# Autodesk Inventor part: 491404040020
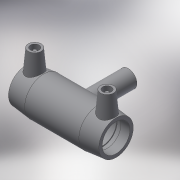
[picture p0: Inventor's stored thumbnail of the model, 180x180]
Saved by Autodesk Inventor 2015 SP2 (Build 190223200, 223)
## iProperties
Created: 2017-06
Part Number: 491404040020
Material: Generic
Description: PLASSON REDUCING TEE 40x20x40
Document SubType Name: Modeling
Designer: KIM
Mass: 57.3761 g
Surface Area: 241.06 cm^2
Volume: 57.3761 cm^3
Density: 1 g/cm^3
Appearance: Default
Author: KIM
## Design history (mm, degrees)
derived "491404.ipt"
feature "Solid1::491404.ipt"
tag "TaggingFeature1"
body "Solid1"
other parameters: "d2" = 56, "d3" = 43, "d4" = 24, "d5" = 50.4, "d6" = 38, "d8" = 168 deg, "d10" = 17.2, "d11" = 5.73333, "d14" = 17.6296, "d17" = 36, "d19" = 3.52592, "d20" = 168 deg, "d22" = 52.08, "d23" = 56, "d25" = 135 deg, "d26" = 84, "d29" = 47, "d30" = 15, "d31" = 48, "d34" = 5 deg, "d35" = 15, "d39" = 5 deg, "d41" = 4, "d42" = 14, "d43" = 0, "d45" = 4, "d46" = 6, "d47" = 0, "d48" = -72, "d51" = 0, "d52" = 16, "d54" = 0, "d55" = 50.4, "d56" = 56, "d57" = 42, "d58" = 135 deg, "d59" = 43, "d60" = 43, "d61" = 135 deg, "d62" = 72, "d72" = 54.6, "d73" = 27.3, "d74" = -72, "d75" = 21, "d77" = 0, "d78" = 16, "d80" = 0, "d82" = 44, "d83" = 0, "d84" = 3, "d85" = 0, "d86" = 14.33333, "d87" = 51.0384, "d88" = 5.73333, "d89" = 3, "d90" = 0, "L_1" = 43, "D_" = 56, "A_" = 47, "d_2" = 12, "H_" = 72
